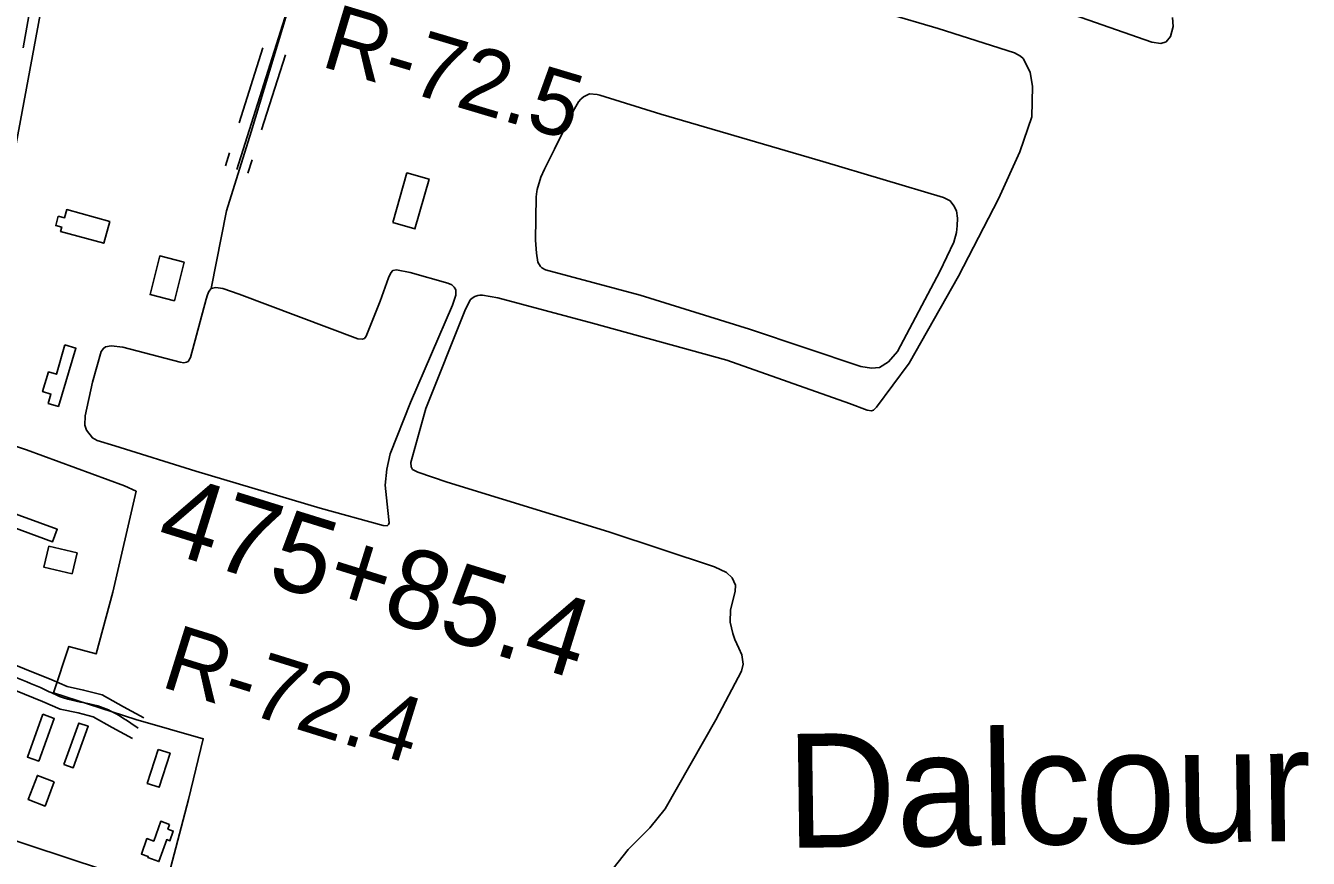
# Model space of a CAD drawing. Extents: x 3683613 to 3738215, y 469626 to 495384.
# Drawn here: x 3704159 to 3705791, y 477641 to 478700 of the extents above; entities that cross this region are included whole.
import ezdxf

# ---------------------------------------------------------------- set-up
doc = ezdxf.new("R2010")
doc.units = 0
for name, color, linetype in [('V-BLDG-OTLN', 7, 'Continuous'), ('V-DTCH-CNTR', 7, 'Continuous'), ('V-LEVE-TOET', 7, 'Continuous'), ('V-RIVR-RANG-IDEN', 7, 'Continuous'), ('V-ROAD-CNTR', 7, 'Continuous'), ('V-SITE-VEGE', 7, 'Continuous'), ('V-SURV-IDEN', 7, 'Continuous'), ('V-TOPO-GNAM-IDEN', 7, 'Continuous')]:
    doc.layers.add(name, color=color, linetype=linetype)

msp = doc.modelspace()

# ---------------------------------------------------------------- linework, layer by layer
at = {"layer": 'V-BLDG-OTLN'}
for points in [[(3704625.8, 478449.4), (3704643.7, 478512.5), (3704671.8, 478504.6), (3704653.8, 478441.4)], [(3704200.1, 478457.7), (3704208, 478455.6), (3704210.8, 478465.8), (3704265.6, 478450.9), (3704258, 478423), (3704203, 478437.9), (3704204.5, 478443.6), (3704196.9, 478445.6)], [(3704360.3, 478399.2), (3704347.9, 478350), (3704316.8, 478357.8), (3704329.2, 478407)], [(3704208.4, 478293.8), (3704222.5, 478289.5), (3704200.3, 478215.4), (3704187.2, 478219.3), (3704190.8, 478231.1), (3704180.2, 478234.3), (3704187.8, 478259.4), (3704197.8, 478256.4)], [(3704128, 478085.2), (3704198.7, 478059.2), (3704192.8, 478043.3), (3704122.2, 478069.2)], [(3704187.9, 478037.7), (3704223.9, 478029.2), (3704217.6, 478002.5), (3704181.5, 478011.1)], [(3704180.5, 477823.8), (3704195, 477818.6), (3704175.3, 477764.2), (3704160.8, 477769.4)], [(3704207.3, 477760.1), (3704226.2, 477812.7), (3704238.2, 477808.5), (3704219.2, 477755.8)], [(3704327.1, 477779.2), (3704342.4, 477774.3), (3704328.5, 477730.9), (3704313.2, 477735.8)], [(3704195, 477737.9), (3704183.3, 477707.1), (3704161.9, 477715.2), (3704173.5, 477746)], [(3704341.7, 477683.8), (3704339.6, 477677.7), (3704346.4, 477675.3), (3704342, 477662.9), (3704338, 477664.3), (3704328.1, 477636.4), (3704314.1, 477641.4), (3704314.6, 477642.8), (3704305.8, 477645.9), (3704312.8, 477665.6), (3704321.6, 477662.5), (3704330.5, 477687.8)]]:
    msp.add_lwpolyline(points, close=True, dxfattribs=at)
at = {"layer": 'V-DTCH-CNTR'}
for points in [[(3704394.7, 478365.6), (3704414.3, 478464.3), (3704445.3, 478564.8), (3704490.9, 478714.8), (3704516.1, 478797.6), (3704353.3, 478838.2), (3704363.8, 478884.8)], [(3704299.2, 478107.5), (3704284.5, 478114.4), (3704159.7, 478160.3), (3704088.6, 478183.9), (3704080.5, 478186.2)], [(3704336.2, 477602.3), (3704365.6, 477715.6), (3704384.6, 477792.6), (3704298.8, 477817.3), (3704194.1, 477851), (3704213.5, 477910.2), (3704248.1, 477900.6), (3704269.4, 477979.3), (3704299.2, 478107.5)], [(3703940.6, 477598.1), (3703969.8, 477702.5), (3704113.2, 477657.5), (3704118.7, 477671.8), (3704256.3, 477626.2)]]:
    msp.add_lwpolyline(points, dxfattribs=at)
at = {"layer": 'V-LEVE-TOET'}
msp.add_lwpolyline([(3704527, 480810.9), (3704510.1, 480703.4), (3704493.6, 480594.1), (3704477.7, 480492.4), (3704461, 480373.9), (3704423.7, 480135.5), (3704413.8, 480049), (3704397.1, 479959.1), (3704381.1, 479868.6), (3704359, 479773.1), (3704341.9, 479691.7), (3704326.4, 479615.9), (3704312.3, 479534), (3704291.5, 479424.4), (3704275.5, 479337.1), (3704262.9, 479253.9), (3704244.7, 479159), (3704226.9, 479062.1), (3704213.4, 478985.4), (3704193.8, 478883.6), (3704173.1, 478772.8), (3704155.4, 478671.7)], dxfattribs=at)
at = {"layer": 'V-ROAD-CNTR'}
for points in [[(3703726.6, 476963.3), (3703726.6, 476963.3), (3704073.6, 478169.6), (3704082.9, 478208.9), (3704324.3, 479507.4), (3704405, 479907.3), (3704509.6, 480585.2)], [(3704586.3, 479020), (3704427.1, 478516.9)], [(3704460.4, 478671.8), (3704430.2, 478576.4)], [(3704489, 478662.7), (3704458.8, 478567.4)], [(3704418.1, 478538.3), (3704412.8, 478521.5)], [(3704446.7, 478529.2), (3704441.4, 478512.4)], [(3704006.5, 477936.6), (3704034.9, 477928.1), (3704057.1, 477921.5), (3704090.3, 477909.3), (3704122.4, 477895.8), (3704157, 477881.8), (3704191.8, 477867.6), (3704211.5, 477859), (3704232.2, 477854.7), (3704255.8, 477848.5), (3704283.2, 477833.5), (3704308.9, 477819.3)], [(3703998.3, 477907.8), (3704047.6, 477893), (3704079.3, 477881.4), (3704111, 477868), (3704145.7, 477854), (3704180.2, 477840), (3704202.3, 477830.3), (3704225.4, 477825.5), (3704244.6, 477820.5), (3704268.7, 477807.2), (3704294.5, 477793)]]:
    msp.add_lwpolyline(points, dxfattribs=at)
msp.add_spline([(3704008.9, 477920.2), (3704052.4, 477907.3), (3704116.7, 477881.9), (3704186, 477853.8), (3704206.9, 477844.6), (3704250.2, 477834.5), (3704301.7, 477806.2)], degree=3, dxfattribs=at)
at = {"layer": 'V-SITE-VEGE'}
for p, q in [((3705319.6, 478696.2), (3705186.3, 478735.8)), ((3705456.5, 478725.9), (3705591.5, 478678.8)), ((3705618.5, 478698.9), (3705617.6, 478710.4)), ((3705416.6, 478665.3), (3705319.6, 478696.2)), ((3705615, 478686), (3705618.5, 478698.9)), ((3705591.5, 478678.8), (3705603, 478677)), ((3705603, 478677), (3705609.6, 478679.2)), ((3705609.6, 478679.2), (3705615, 478686)), ((3705424.5, 478661.1), (3705416.6, 478665.3)), ((3705427.7, 478658.1), (3705424.5, 478661.1)), ((3705436.5, 478640.6), (3705427.7, 478658.1)), ((3705439.4, 478622.6), (3705436.5, 478640.6)), ((3705438.8, 478584), (3705439.4, 478622.6)), ((3705423.4, 478539.5), (3705438.8, 478584)), ((3705396.2, 478479.4), (3705423.4, 478539.5)), ((3705345.4, 478381), (3705396.2, 478479.4)), ((3705282.7, 478270.7), (3705345.4, 478381)), ((3704717.4, 478337.2), (3704724.3, 478351.1)), ((3704724.3, 478351.1), (3704726.5, 478353.3)), ((3704726.5, 478353.3), (3704730.2, 478355.5)), ((3704730.2, 478355.5), (3704734, 478356.7)), ((3704734, 478356.7), (3704736.4, 478357.2)), ((3704736.4, 478357.2), (3704739.8, 478357)), ((3704739.8, 478357), (3704759.3, 478353.7)), ((3704759.3, 478353.7), (3704879.9, 478321.5)), ((3704667.8, 478213), (3704717.4, 478337.2)), ((3704879.9, 478321.5), (3705050.8, 478274.4)), ((3705050.8, 478274.4), (3705206.7, 478219.3)), ((3705241.2, 478214.5), (3705282.7, 478270.7)), ((3704648.8, 478144.3), (3704667.8, 478213)), ((3705206.7, 478219.3), (3705229.1, 478210.6)), ((3705229.1, 478210.6), (3705234.9, 478209.7)), ((3705234.9, 478209.7), (3705237.1, 478210.6)), ((3705237.1, 478210.6), (3705241.2, 478214.5)), ((3704649, 478138.6), (3704648.8, 478144.3)), ((3704650.7, 478135.4), (3704649, 478138.6)), ((3704657.5, 478131.8), (3704650.7, 478135.4)), ((3704694.7, 478119.2), (3704657.5, 478131.8)), ((3704900.6, 478055.9), (3704694.7, 478119.2)), ((3705035.1, 478011.6), (3704900.6, 478055.9)), ((3705050.1, 478004.2), (3705035.1, 478011.6)), ((3705057.5, 477997.5), (3705050.1, 478004.2)), ((3705061.6, 477987.9), (3705057.5, 477997.5)), ((3705055.3, 477956.8), (3705061.1, 477979.9)), ((3705061.1, 477979.9), (3705061.6, 477987.9)), ((3705055.1, 477941.2), (3705055.3, 477956.8)), ((3705058.1, 477926.4), (3705055.1, 477941.2)), ((3705061, 477918.9), (3705058.1, 477926.4)), ((3705066, 477908), (3705061, 477918.9)), ((3705069.7, 477899.5), (3705066, 477908)), ((3705071.3, 477887.6), (3705069.7, 477899.5)), ((3705036.5, 477816.6), (3705069.4, 477878.6)), ((3705069.4, 477878.6), (3705071.3, 477887.6)), ((3704972.1, 477703.5), (3705036.5, 477816.6)), ((3704952.5, 477679.2), (3704972.1, 477703.5)), ((3704925, 477652), (3704952.5, 477679.2)), ((3704875.6, 477589.2), (3704925, 477652))]:
    msp.add_line(p, q, dxfattribs=at)
for points in [[(3704808.2, 478482.3), (3704808.8, 478488.9), (3704809.4, 478491.5), (3704813.9, 478507.1), (3704818.5, 478517.3), (3704831.4, 478542.8), (3704855.3, 478591.3), (3704862, 478602.9), (3704864.8, 478606.2), (3704868.4, 478609.3), (3704873.4, 478611.8), (3704876, 478613), (3704885.9, 478612.1), (3704888.9, 478611.6), (3704966.9, 478587.3), (3705172.7, 478527), (3705326.3, 478481.1), (3705334.7, 478476.9), (3705339.6, 478470.7), (3705342.8, 478464.2), (3705344, 478455), (3705343.9, 478445.3), (3705343, 478436.6), (3705339.4, 478424.3), (3705321.6, 478387.3), (3705267.8, 478285.3), (3705256.4, 478272.4), (3705244.8, 478264.8), (3705234.7, 478264), (3705221.3, 478266.1), (3705079.7, 478313.8), (3704940.6, 478356.9), (3704820, 478389.3), (3704815.4, 478391.9), (3704813.5, 478393.3), (3704810.3, 478398.8), (3704808.4, 478410.4), (3704807.3, 478427.1)], [(3704272.1, 478165.2), (3704249.5, 478172.2), (3704243.6, 478175.5), (3704236, 478185.1), (3704234, 478191.6), (3704234.1, 478203.3), (3704243.4, 478246.5), (3704254.7, 478285.2), (3704257.5, 478289.2), (3704260.3, 478291.2), (3704267.5, 478292.6), (3704282.4, 478290.7), (3704355.1, 478271.6), (3704359.7, 478271.1), (3704363.2, 478271.6), (3704365.2, 478272.8), (3704368.2, 478277.7), (3704388.1, 478351.9), (3704389.9, 478357.3), (3704391.8, 478361.7), (3704394.7, 478365.6), (3704400.5, 478366.7), (3704409.5, 478365.6), (3704430.1, 478358.2), (3704581.3, 478301.5), (3704586.6, 478301), (3704589.5, 478302), (3704591.7, 478304.8), (3704609.5, 478349.5), (3704620, 478379.2), (3704623.1, 478385.5), (3704625.6, 478388.2), (3704630.2, 478389.2), (3704647.7, 478385.9), (3704695.7, 478372.1), (3704700.6, 478370.2), (3704703.8, 478367), (3704705.9, 478363.9), (3704706, 478357.2), (3704701.5, 478344.2), (3704648.1, 478220.5), (3704622.3, 478155.1), (3704617.9, 478135.7), (3704616, 478115.1), (3704619.4, 478082.9), (3704620.9, 478067.3), (3704620.2, 478065.1), (3704618.4, 478063.5), (3704613.5, 478064), (3704533.2, 478086), (3704374.9, 478133)]]:
    msp.add_lwpolyline(points, close=True, dxfattribs=at)

# ---------------------------------------------------------------- texts
at = {"layer": 'V-RIVR-RANG-IDEN'}
for s, rotation, p in [('R-72.5', 343.3927, (3704532.1, 478648.8)), ('R-72.4', 342.6903, (3704328.3, 477859.6))]:
    msp.add_text(s, height=83, rotation=rotation, dxfattribs=at).set_placement(p)
at = {"layer": 'V-SURV-IDEN'}
msp.add_text('475+85.4', height=100, rotation=342.7161, dxfattribs=at).set_placement((3704321.1, 478035.1))
at = {"layer": 'V-TOPO-GNAM-IDEN'}
msp.add_text('Dalcour', height=145, rotation=0.7751, dxfattribs=at).set_placement((3705127, 477653.7))

doc.saveas('drawing.dxf')
